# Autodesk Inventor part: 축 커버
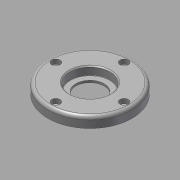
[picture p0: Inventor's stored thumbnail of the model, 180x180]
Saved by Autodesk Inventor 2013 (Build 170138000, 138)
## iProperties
Created: 2015-10
Part Number: 축 커버
Document SubType Name: Modeling
Designer: mdu
Density: 1 g/cm^3
Material: 강철, 연강
Author: mdu
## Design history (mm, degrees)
sketch "스케치1"
  geometry: C1 r 40 at (0, 0) reference; C2 r 26 at (0, 0) reference; 1 further point
  node "참조1"
  node "참조2"
extrude "돌출1" new body sketch "스케치1" distance "d0" = 10; taper "d1" = 0 deg
extrude "돌출2" join sketch "스케치1" distance "d2" = 3; taper "d3" = 0 deg
hole "구멍1" diameter "d6" = 27; stored, may be unused: countersink angle "d10" = 90 deg, drill point angle "d12" = 118 deg; dims "d4" = 10, "d5" = 10, "d7" = 6, "d8" = 38, "d9" = 8, "d11" = 8
sketch "스케치2"
  geometry: C1 r 20 at (0, 0); 1 further point
  constraints: 1 centre point, 1 coincident
  dimensions: "d13" = 40 diameter of C1
extrude "돌출3" cut sketch "스케치2" distance "d14" = 3; taper "d15" = 0 deg
sketch "스케치3"
  geometry: C1 r 1.621 at (0, 32.5) reference; 1 further point
hole "구멍2" sketch "스케치3" at (0, 32.5) diameter "d16" = 4.5; stored, may be unused: countersink angle "d20" = 90 deg, drill point angle "d22" = 118 deg; dims "d17" = 6, "d18" = 8, "d19" = 4.4, "d21" = 8
fillet "모깎기1" dims "d26" = 3, "d27" = 0.3
chamfer "모따기1" distance "d28" = 1; stored, may be unused: second distance "d29" = 2, angle "d30" = 45 deg
node "솔리드1"
pattern_circular "원형 패턴1" dims angle "d24" = 360 deg
node "참조3"
